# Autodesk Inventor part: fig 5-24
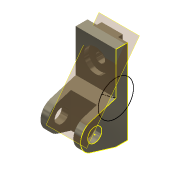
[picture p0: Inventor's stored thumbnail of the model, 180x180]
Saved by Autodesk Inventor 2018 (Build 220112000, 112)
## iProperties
Shininess: 65.0
Angle Display Precision: 2
Document Length Units: 11269
Document Angle Units: 11279
Document Time Units: 11290
Document Mass Units: 11283
Document Length Units Precision: 3
Document Angle Units Precision: 2
Compacted: False
Created: 2001-11
Part Number: fig 5-24
Document SubType Name: Modeling
Designer: Renu Muthoo
Density: 1 g/cm^3
Material: Generic
Appearance: Metal-Titanium (Polished)
Density: 0.0
Volumn: 0.0
Area: 0.0
PropertySet Name: Model Information
Control State: 0
Master: False
Checked Out: False
Author: Renu Muthoo
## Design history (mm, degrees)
node "Sketch1"
sketch "Sketch2"
  geometry: L1 (33.257, 104.664)-(33.257, -75.336); L2 (33.257, -75.336)-(8.257, -75.336); L3 (8.257, -75.336)-(-45.451, -59.045); L4 (-45.451, -1.628)-(8.257, 14.664); L5 (8.257, 14.664)-(8.257, 104.664); L6 (8.257, 104.664)-(33.257, 104.664); C1 r 15 at (-36.743, -30.336); A1 r 30 centre (-36.743, -30.336) between (-45.451, -1.628) and (-45.451, -59.045)
  constraints: 12 end point, 2 centre point, 2 equal length, 2 parallel, 2 point on circle, 2 tangent, 1 coincident, 1 perpendicular, 1 vertical
  dimensions: "d0" = 180 distance of L1.start L1.end; "d1" = 30 radius of A1; "d2" = 25 distance of L5.end L1.start; "d3" = 45 distance from line of L2 A1.centre; "d4" = 70 distance from line of L1 A1.centre; "d5" = 30 diameter of C1
extrude "Extrusion1" new body sketch "Sketch2" distance "d6" = 85; taper "d7" = 0 deg
workplane "Work Plane1"
sketch "Sketch3"
  geometry: L1 (15, 62.364)-(70, 62.364); L2 (70, 62.364)-(70, -52.386); L3 (70, -52.386)-(15, -52.386); L4 (15, -52.386)-(15, 62.364); L5 (0, -45)-(0, -28.708) reference
  constraints: 8 end point, 2 parallel, 1 horizontal, 1 perpendicular
  dimensions: "d8" = 55 distance of L1.start L1.end; "d9" = 15 distance between parallel lines of L5 L4
extrude "Extrusion2" cut sketch "Sketch3" distance "d10" = 50; taper "d11" = 0 deg
sketch "Sketch4"
  geometry: L1 (0, 25)-(85, 25) reference; L2 (0, 0)-(0, 25) reference; L3 (20, 25)-(65, 25); L4 (65, 25)-(65, 35); L5 (65, 35)-(20, 35); L6 (20, 35)-(20, 25)
  constraints: 8 end point, 2 parallel, 1 horizontal, 1 perpendicular, 1 point on line
  dimensions: "d12" = 45 distance of L4.end L5.end; "d13" = 10 distance of L3.end L4.end; "d14" = 20 distance between parallel lines of L2 L6
extrude "Extrusion3" join sketch "Sketch4" stored distance "d15" = 50; taper "d16" = 0 deg
sketch "Sketch5"
  geometry: L1 (85, 0)-(85, 90) reference; L2 (0, 90)-(85, 90) reference; 1 further point
  dimensions: "d17" = 42 distance from line of L2 point (42.5, 48); "d18" = 42.5 distance from line of L1 point (42.5, 48)
hole "Hole1" sketch "Sketch5" at (42.5, 48) diameter "d19" = 20; stored, may be unused: countersink angle "d23" = 82 deg, drill point angle "d25" = 118 deg; dims "d20" = 6, "d21" = 50, "d22" = 10, "d24" = 8
sketch "Sketch8"
  geometry: L1 (75.336, 33.257)-(75.336, 8.257) reference; L2 (-104.664, 33.257)-(75.336, 33.257) reference; L3 (-104.664, 8.257)-(-104.664, 33.257) reference; L4 (-14.664, 8.257)-(-104.664, 8.257) reference; L5 (1.628, -45.451)-(-14.664, 8.257) reference; L6 (75.336, 8.257)-(59.045, -45.451) reference; C1 r 15 at (30.336, -36.743) reference; C2 r 37.437 at (-14.664, 8.257); A1 r 30 centre (30.336, -36.743) between (1.628, -45.451) and (59.045, -45.451) reference
  constraints: 1 centre point, 1 coincident
sketch "Sketch9"
  geometry: L1 (75.336, 33.257)-(75.336, 8.257) reference; L2 (-14.664, 8.257)-(-104.664, 8.257) reference; L3 (1.628, -45.451)-(-14.664, 8.257) reference; L4 (75.336, 8.257)-(59.045, -45.451) reference; L5 (-14.664, 8.257)-(-37, -21.743); C1 r 15 at (30.336, -36.743) reference; A1 r 30 centre (30.336, -36.743) between (1.628, -45.451) and (59.045, -45.451) reference
  constraints: 2 end point
workplane "Work Plane11"
body "Solid1"
